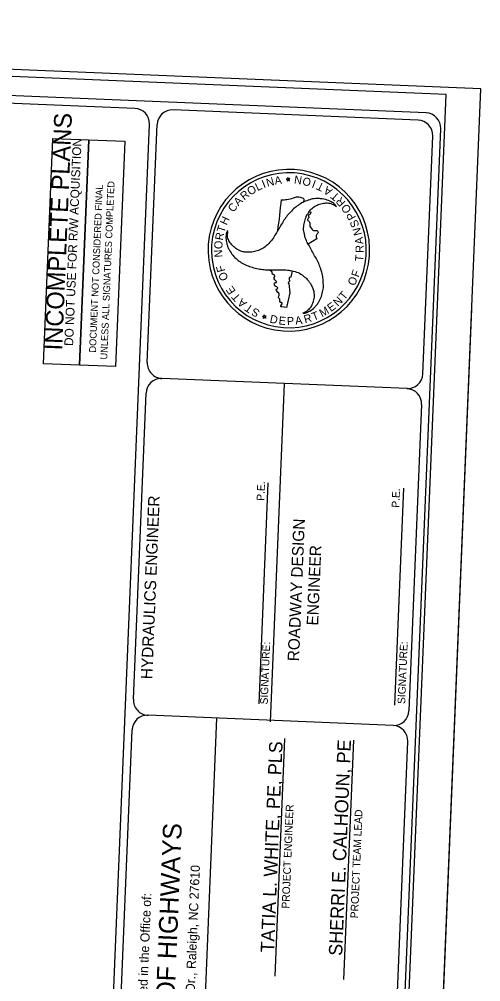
# Model space of a CAD drawing. Extents: x 2264506 to 2267635, y 507918 to 512596.
# Drawn here: x 2266882 to 2267635, y 511027 to 512596 of the extents above; entities that cross this region are included whole.
import ezdxf

# ---------------------------------------------------------------- set-up
doc = ezdxf.new("R2010")
doc.units = 0
for name, color, linetype in [('Matchline', 7, 'Continuous'), ('Prop Horizontal Alignment', 7, 'Continuous'), ('Prop Horizontal Alignment Curve and Spiral Data', 7, 'Continuous'), ('Prop Horizontal Alignment Direction Label', 7, 'Continuous'), ('Prop Horizontal Alignment Station Label', 7, 'Continuous'), ('Prop Horizontal Alignment Tick Label', 7, 'Continuous'), ('Prop Horizontal Alignment Tick Large', 7, 'Continuous')]:
    doc.layers.add(name, color=color, linetype=linetype)

msp = doc.modelspace()

# ---------------------------------------------------------------- linework, layer by layer
at = {"layer": 'Matchline'}
msp.add_line((2267446.4, 507917.5), (2267620.2, 512123.9), dxfattribs=at)
at = {"layer": 'Prop Horizontal Alignment Curve and Spiral Data'}
msp.add_lwpolyline([(2266980.6, 512032), (2266921.9, 512034.4), (2266937.1, 512401.6), (2266995.8, 512399.2)], close=True, dxfattribs=at)
at = {"layer": 'Prop Horizontal Alignment Direction Label'}
for p, q in [((2266980.6, 512032), (2266995.8, 512399.2)), ((2266995.8, 512399.2), (2267054.5, 512396.8)), ((2267054.5, 512396.8), (2267039.3, 512029.6)), ((2267039.3, 512029.6), (2266980.6, 512032))]:
    msp.add_line(p, q, dxfattribs=at)
at = {"layer": 'Prop Horizontal Alignment Station Label'}
for p, q in [((2266948.1, 508877.5), (2267094.6, 512424.5)), ((2267091.1, 512036.3), (2267107.1, 512424)), ((2267344.7, 512349.1), (2267344.7, 512349.1)), ((2267319.8, 512335.5), (2267317.5, 512335.1)), ((2267317.5, 512335.1), (2267319.5, 512334.1)), ((2267319.5, 512334.1), (2267319.1, 512331.9)), ((2267319.1, 512331.9), (2267320.7, 512333.5)), ((2267320.1, 512337.8), (2267319.8, 512335.5)), ((2267321.1, 512335.7), (2267320.1, 512337.8)), ((2267320.7, 512333.5), (2267322.8, 512332.4)), ((2267323.4, 512336), (2267321.1, 512335.7)), ((2267321.8, 512334.4), (2267323.4, 512336)), ((2267322.8, 512332.4), (2267321.8, 512334.4)), ((2267221.6, 512251.1), (2267221.8, 512250.8)), ((2267221.6, 512251.1), (2267221.8, 512250.8)), ((2267303.7, 512251), (2267303.7, 512251)), ((2267367.4, 512237.9), (2267353.6, 512229.1)), ((2267353.6, 512229.1), (2267353.6, 512229.1)), ((2267327.2, 512185.8), (2267325.3, 512175.5)), ((2267321.7, 512165), (2267323.4, 512150.1)), ((2267323.4, 512150.1), (2267318.2, 512125.7)), ((2267281.3, 512111.7), (2267281.7, 512114)), ((2267281.7, 512114), (2267282.7, 512111.9)), ((2267318.2, 512125.7), (2267310.4, 512127.3)), ((2267279.1, 512111.3), (2267281.3, 512111.7)), ((2267281, 512110.3), (2267279.1, 512111.3)), ((2267280.6, 512108.1), (2267281, 512110.3)), ((2267282.3, 512109.6), (2267280.6, 512108.1)), ((2267284.3, 512108.6), (2267282.3, 512109.6)), ((2267282.7, 512111.9), (2267285, 512112.2)), ((2267285, 512112.2), (2267283.3, 512110.6)), ((2267283.3, 512110.6), (2267284.3, 512108.6)), ((2267514.7, 511993.7), (2267115, 512010.3)), ((2267292, 511450.8), (2267314.8, 512002)), ((2267068.4, 511487.3), (2267089, 511986.3)), ((2267273.3, 511480.1), (2267288.2, 511840.4)), ((2267494.8, 511477.8), (2267509.4, 511831.3)), ((2267492, 511444.8), (2267092.4, 511461.3)), ((2267204.2, 511456.7), (2267172.7, 510694.8)), ((2267036.9, 510725.5), (2267066.3, 511437.3)), ((2267299.4, 511036), (2267315.4, 511423.6)), ((2267411.7, 511030.5), (2267427.8, 511420.8))]:
    msp.add_line(p, q, dxfattribs=at)
for points in [[(2267545.8, 512443.4), (2264973, 512549.7)], [(2267070.7, 512450.5), (2264985, 512536.7)], [(2267532.8, 512431.4), (2267133.1, 512448)], [(2267417, 508720.6), (2267569.8, 512417.4)], [(2267540.7, 512017.7), (2267556.7, 512405.4)], [(2267518, 511468.7), (2267538.6, 511967.7)], [(2267486.6, 510706.9), (2267516, 511418.8)]]:
    msp.add_lwpolyline(points, dxfattribs=at)
for centre, radius, start, end in [((2267069.5, 512425.6), 25, 357.6342, 87.6342), ((2267132, 512423), 25, 87.6342, 177.6342), ((2267544.6, 512418.4), 25, 357.6342, 87.6342), ((2267531.6, 512406.5), 25, 357.6342, 87.6342), ((2267322, 512219.3), 131.8, 80.0553, 260.0553), ((2267322, 512219.3), 131.8, 260.0553, 80.0553), ((2267322, 512219.3), 126.3, 80.0553, 260.0553), ((2267322, 512219.3), 126.3, 260.0553, 80.0553), ((2266617.1, 512357.6), 694.9, 351.1728, 355.3789), ((2266617.1, 512357.6), 694.9, 345.7338, 345.8334), ((2267116.1, 512035.2), 25, 177.6342, 267.6342), ((2267114, 511985.3), 25, 87.6342, 177.6342), ((2267515.6, 512018.7), 25, 267.6342, 357.6342), ((2267513.5, 511968.8), 25, 357.6342, 87.6342), ((2267093.3, 511486.3), 25, 177.6342, 267.6342), ((2267091.2, 511436.3), 25, 87.6342, 177.6342), ((2267492.9, 511469.8), 25, 267.6342, 357.6342), ((2267490.9, 511419.8), 25, 357.6342, 87.6342)]:
    msp.add_arc(centre, radius, start, end, dxfattribs=at)
for points in [[(2267399.7, 512290.4), (2267397.9, 512292.8), (2267391, 512298.2), (2267382.3, 512301.8), (2267381.5, 512302), (2267376.5, 512303), (2267370.6, 512303.4), (2267360.8, 512302.9), (2267351.3, 512299.9), (2267347.3, 512298.6), (2267343.2, 512296.3), (2267335, 512291), (2267328.1, 512285.1), (2267320.9, 512277.4), (2267315.2, 512270.2), (2267310.2, 512262), (2267305.4, 512253.7), (2267300.6, 512245.9), (2267295.4, 512237.6), (2267289.4, 512230.5), (2267288.8, 512229.9), (2267281.1, 512223.2), (2267272.3, 512219.1), (2267263.6, 512216.7), (2267259.1, 512216.2), (2267253.5, 512216.4), (2267250.2, 512216.4), (2267243.7, 512218), (2267235.4, 512222.2), (2267229, 512228.2), (2267224.3, 512234.7), (2267221.9, 512242.6), (2267221.8, 512250.8), (2267221.6, 512251.1)], [(2267309.7, 512301.6), (2267318.7, 512301.9), (2267329.7, 512304.7), (2267335.8, 512306.6), (2267340.6, 512305.7), (2267346.1, 512303.6), (2267345.7, 512298)], [(2267345.8, 512297.9), (2267343.2, 512296.3), (2267335, 512291), (2267328.1, 512285.1), (2267320.9, 512277.4), (2267315.2, 512270.2), (2267310.2, 512262), (2267305.4, 512253.7), (2267303.7, 512251)], [(2267345, 512116.5), (2267348.1, 512116.9), (2267356.2, 512120.2), (2267363.6, 512125.9), (2267364.1, 512126.6), (2267367.6, 512130.4), (2267370.8, 512135.3), (2267375.3, 512144.1), (2267377.4, 512153.7), (2267378.3, 512157.8), (2267378.3, 512162.7), (2267377.8, 512172.2), (2267376.3, 512181.1), (2267373.2, 512191.3), (2267369.9, 512199.8), (2267365.2, 512208.2), (2267360.4, 512216.5), (2267356, 512224.7), (2267351.5, 512233.2), (2267348.2, 512242), (2267348, 512243), (2267346.1, 512253), (2267346.9, 512262.5), (2267349.2, 512271.2), (2267351, 512275.6), (2267354.1, 512280.2), (2267355.6, 512283.1), (2267360.3, 512287.9), (2267368, 512292.9), (2267376.4, 512295.5), (2267384.5, 512296.3), (2267392.5, 512294.5), (2267399.7, 512290.4)], [(2267353.6, 512229.1), (2267351.5, 512233.2), (2267348.2, 512242), (2267348, 512243), (2267346.1, 512253), (2267346.9, 512262.5), (2267349.2, 512271.2), (2267351, 512275.6), (2267354.1, 512280.2), (2267355.6, 512282.9)], [(2267355.6, 512282.8), (2267357.7, 512281.2), (2267357.5, 512279.2), (2267354.1, 512276.3), (2267354.3, 512272), (2267352.8, 512270.2), (2267352.5, 512269), (2267355.8, 512265.3), (2267356, 512260.9), (2267359.8, 512253.3), (2267362.4, 512251.4), (2267368.8, 512250.8), (2267369.7, 512249), (2267369, 512247), (2267366.7, 512243.2), (2267367.4, 512237.9)], [(2267221.8, 512250.8), (2267220.5, 512248), (2267219.4, 512239.3), (2267220.6, 512230.1), (2267220.9, 512229.2), (2267222.5, 512224.4), (2267225.1, 512219.2), (2267230.5, 512211), (2267237.8, 512204.1), (2267240.9, 512201.4), (2267244.9, 512199), (2267253.6, 512194.5), (2267262.2, 512191.5), (2267272.4, 512189.1), (2267281.5, 512187.7), (2267291.1, 512187.5), (2267300.7, 512187.5), (2267310, 512187.3), (2267319.6, 512186.9), (2267328.9, 512185.3), (2267329.7, 512185.1), (2267339.3, 512181.7), (2267347.2, 512176.2), (2267353.6, 512169.8), (2267356.4, 512166.2), (2267359, 512161.2), (2267360.6, 512158.4), (2267362.5, 512152), (2267363, 512142.7), (2267361, 512134.1), (2267357.7, 512126.8), (2267352.2, 512120.8), (2267345, 512116.5)], [(2267310.4, 512127.3), (2267309.6, 512127.2), (2267309, 512128.6), (2267311.2, 512132), (2267309.9, 512134.1), (2267308.3, 512134.3), (2267307, 512136.1), (2267307.9, 512138.5), (2267305.4, 512141.3), (2267305.3, 512143.4), (2267306.1, 512147.8), (2267301.8, 512153.9), (2267301.8, 512156.2), (2267303.3, 512156.5), (2267303.8, 512157.8), (2267299.9, 512160.8), (2267299.4, 512161.4), (2267298.5, 512165.8), (2267299.4, 512166.8), (2267301.4, 512166.7), (2267301.9, 512167.2), (2267301.2, 512168.7), (2267299.2, 512171), (2267298, 512174.6), (2267299.2, 512178.3), (2267296.2, 512179.5), (2267294, 512184.5), (2267292.3, 512185.8), (2267290.5, 512186.3)], [(2267290.8, 512187.5), (2267291.1, 512187.5), (2267300.7, 512187.5), (2267310, 512187.3), (2267319.6, 512186.9), (2267327.2, 512185.8)], [(2267325.3, 512175.5), (2267323.2, 512174.9), (2267322.3, 512173), (2267323.2, 512170), (2267322.7, 512168), (2267320.7, 512166.1), (2267321.7, 512165)]]:
    msp.add_spline(points, degree=3, dxfattribs=at)
at = {"layer": 'Prop Horizontal Alignment Tick Label'}
msp.add_lwpolyline([(2267406.5, 508310.6), (2267578.5, 512473.3), (2264943, 512582.2), (2264771, 508419.5)], close=True, dxfattribs=at)
at = {"layer": 'Prop Horizontal Alignment Tick Large'}
msp.add_lwpolyline([(2264887.3, 512595.8), (2264713.6, 508389.4), (2267461.2, 508275.9), (2267635, 512482.3)], close=True, dxfattribs=at)

# ---------------------------------------------------------------- texts
at = {"layer": 'Prop Horizontal Alignment'}
for s, p in [('TATIA L. WHITE, PE, PLS', (2267297.7, 511074.2)), ('SHERRI E. CALHOUN, PE', (2267408.9, 511068.9))]:
    msp.add_text(s, height=21.875, rotation=87.6342, dxfattribs=at).set_placement(p)
at = {"layer": 'Prop Horizontal Alignment Curve and Spiral Data'}
for s, height, p in [('INCOMPLETE PLANS', 28.8, (2266952.3, 512055.6)), ('DO NOT USE FOR R/W ACQUISITION', 14.4, (2266970, 512063))]:
    msp.add_text(s, height=height, rotation=87.6342, dxfattribs=at).set_placement(p)
at = {"layer": 'Prop Horizontal Alignment Direction Label'}
for s, p in [('DOCUMENT NOT CONSIDERED FINAL', (2267007.3, 512052.3)), ('UNLESS ALL SIGNATURES COMPLETED', (2267025.7, 512041))]:
    msp.add_text(s, height=11.25, rotation=87.6342, dxfattribs=at).set_placement(p)
at = {"layer": 'Prop Horizontal Alignment Station Label'}
for s, height, rotation, p in [('I', 13.2, 21.6507, (2267281.1, 512320.2)), ('N', 13.1, 15.9506, (2267287.1, 512322.5)), ('A', 13.1, 8.5186, (2267299.5, 512325.9)), ('N', 13.1, 172.2634, (2267344.2, 512339.5)), ('O', 13.1, 165.0154, (2267359.5, 512335.5)), ('I', 13.2, 159.8798, (2267367.5, 512332.7)), ('R', 13.1, 38.9934, (2267249.1, 512300.2)), ('O', 13.2, 31.8738, (2267258.9, 512308.1)), ('L', 13.1, 25.6401, (2267270.8, 512315.5)), ('T', 13.1, 154.2299, (2267380.9, 512326.3)), ('A', 13.2, 147.1454, (2267394.1, 512318)), ('A', 13.1, 45.3573, (2267239.7, 512290.6)), ('T', 13.1, 139.0584, (2267405.5, 512308.4)), ('R', 13.2, 132.9586, (2267415.5, 512297.9)), ('C', 13.1, 52.8543, (2267231.7, 512280.2)), ('O', 13.2, 125.7695, (2267424.9, 512285.1)), ('H', 13.1, 65.1967, (2267220.6, 512259.1)), ('P', 13.1, 119.0775, (2267431.8, 512272.8)), ('T', 13.2, 72.2814, (2267216.6, 512246.9)), ('S', 13.1, 111.8857, (2267437.3, 512259.4)), ('N', 13.1, 104.6752, (2267441.3, 512245.1)), ('R', 13.1, 78.931, (2267214.2, 512234.6)), ('A', 13.1, 97.6436, (2267443.7, 512229.7)), ('O', 13.2, 85.541, (2267213.1, 512220.7)), ('R', 13.2, 90.8904, (2267444.1, 512215.2)), ('N', 13.1, 93.0391, (2267213.7, 512207.9)), ('T', 13.1, 83.9338, (2267442.7, 512200.4)), ('F', 13.2, 105.126, (2267218.5, 512185.5)), ('O', 13.2, 112.2728, (2267223.7, 512172.6)), ('O', 13.1, 63.8594, (2267428.8, 512160.1)), ('F', 13.1, 71.0246, (2267435.6, 512174.4)), ('E', 13.1, 124.2122, (2267235.8, 512152.7)), ('T', 13.1, 131.3279, (2267244.3, 512143)), ('N', 13.2, 43.7137, (2267401.8, 512126.9)), ('T', 13.1, 50.5557, (2267412.5, 512137.3)), ('A', 13.2, 138.3831, (2267254.4, 512134)), ('T', 13.2, 145.4354, (2267264.9, 512126.6)), ('E', 13.1, 36.7421, (2267390.6, 512118.3)), ('S', 13.1, 151.8115, (2267275.9, 512120.6)), ('D', 13.1, 347.9083, (2267290, 512101.5)), ('R', 13.1, 15.3898, (2267348.4, 512100.1)), ('T', 13.1, 22.0403, (2267362.4, 512104.1)), ('M', 13.1, 29.2754, (2267376.1, 512109.9)), ('E', 13.1, 354.1962, (2267304.8, 512098.5)), ('P', 13.1, 1.7286, (2267319, 512097.3)), ('A', 13.1, 8.3211, (2267333.1, 512097.7)), ('P.E.', 12.5, 87.6342, (2267281.8, 511810.7)), (' HYDRAULICS ENGINEER', 18.75, 87.6342, (2267098.9, 511512.8)), ('P.E.', 12.5, 87.6342, (2267502, 511799.4)), ('ROADWAY DESIGN', 18.748, 87.6342, (2267338.6, 511549)), ('ENGINEER', 18.75, 87.6342, (2267369.7, 511607.3)), ('SIGNATURE:', 12.5, 87.6342, (2267287.4, 511478.8)), ('SIGNATURE:', 12.5, 87.6342, (2267511.6, 511479.4)), ('PROJECT ENGINEER', 12.499, 87.6342, (2267322.7, 511146)), ('PROJECT TEAM LEAD', 12.499, 87.6342, (2267434.8, 511130.2)), ('DIVISION OF HIGHWAYS', 30.468, 87.6342, (2267127.7, 510805.5)), ('1000 Birch Ridge Dr., Raleigh, NC 27610', 15, 87.6342, (2267161.9, 510850.4)), ('Prepared in the Office of:', 14.998, 87.6342, (2267088.6, 510948.5))]:
    msp.add_text(s, height=height, rotation=rotation, dxfattribs=at).set_placement(p)

doc.saveas('drawing.dxf')
